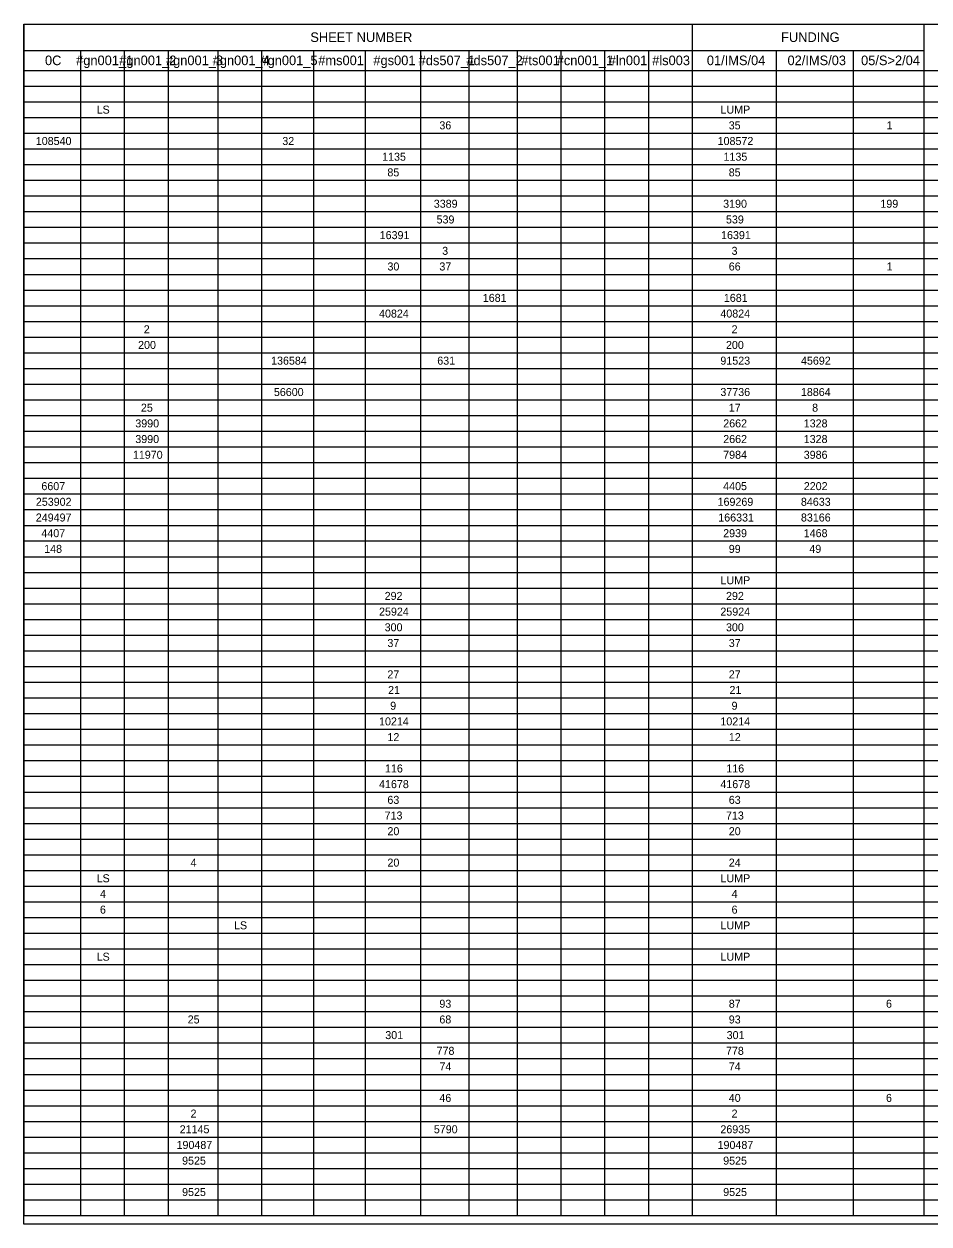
# Model space of a CAD drawing. Extents: x -542 to 295, y -281 to 32.
# Drawn here: x -416.36 to -400.52, y -10.59 to 10.41 of the extents above; entities that cross this region are included whole.
import ezdxf

# ---------------------------------------------------------------- set-up
doc = ezdxf.new("R2010")
doc.units = 0
for name, color, linetype in [('SC_Scratch1', 7, 'Continuous'), ('SH_Data', 7, 'Continuous'), ('SH_Text', 7, 'Continuous')]:
    doc.layers.add(name, color=color, linetype=linetype)

msp = doc.modelspace()

# ---------------------------------------------------------------- linework, layer by layer
at = {"layer": 'SC_Scratch1'}
msp.add_lwpolyline([(-416.359, 10.407), (-385.859, 10.407), (-385.859, -10.593), (-416.359, -10.593)], close=True, dxfattribs=at)
at = {"layer": 'SH_Data'}
for p, q in [((-416.359, 10.407), (-385.859, 10.407)), ((-416.359, 10.407), (-416.359, -10.444)), ((-404.663, 10.407), (-404.663, -10.444)), ((-400.608, 10.407), (-400.608, -10.444)), ((-416.359, 9.946), (-400.608, 9.946)), ((-415.369, 9.946), (-415.369, -10.444)), ((-414.603, 9.946), (-414.603, -10.444)), ((-413.836, 9.946), (-413.836, -10.444)), ((-412.964, 9.946), (-412.964, -10.444)), ((-412.198, 9.946), (-412.198, -10.444)), ((-411.293, 9.946), (-411.293, -10.444)), ((-410.388, 9.946), (-410.388, -10.444)), ((-409.42, 9.946), (-409.42, -10.444)), ((-408.569, 9.946), (-408.569, -10.444)), ((-407.728, 9.946), (-407.728, -10.444)), ((-406.962, 9.946), (-406.962, -10.444)), ((-406.195, 9.946), (-406.195, -10.444)), ((-405.429, 9.946), (-405.429, -10.444)), ((-403.194, 9.946), (-403.194, -10.444)), ((-401.843, 9.946), (-401.843, -10.444)), ((-416.359, 9.595), (-385.859, 9.595)), ((-416.359, 9.32), (-385.859, 9.32)), ((-416.359, 9.046), (-385.859, 9.046)), ((-416.359, 8.771), (-385.859, 8.771)), ((-416.359, 8.497), (-385.859, 8.497)), ((-416.359, 8.222), (-385.859, 8.222)), ((-416.359, 7.948), (-385.859, 7.948)), ((-416.359, 7.673), (-385.859, 7.673)), ((-416.359, 7.399), (-385.859, 7.399)), ((-416.359, 7.124), (-385.859, 7.124)), ((-416.359, 6.85), (-385.859, 6.85)), ((-416.359, 6.575), (-385.859, 6.575)), ((-416.359, 6.301), (-385.859, 6.301)), ((-416.359, 6.026), (-385.859, 6.026)), ((-416.359, 5.752), (-385.859, 5.752)), ((-416.359, 5.477), (-385.859, 5.477)), ((-416.359, 5.203), (-385.859, 5.203)), ((-416.359, 4.928), (-385.859, 4.928)), ((-416.359, 4.654), (-385.859, 4.654)), ((-416.359, 4.379), (-385.859, 4.379)), ((-416.359, 4.105), (-385.859, 4.105)), ((-416.359, 3.83), (-385.859, 3.83)), ((-416.359, 3.556), (-385.859, 3.556)), ((-416.359, 3.281), (-385.859, 3.281)), ((-416.359, 3.007), (-385.859, 3.007)), ((-416.359, 2.732), (-385.859, 2.732)), ((-416.359, 2.458), (-385.859, 2.458)), ((-416.359, 2.183), (-385.859, 2.183)), ((-416.359, 1.909), (-385.859, 1.909)), ((-416.359, 1.634), (-385.859, 1.634)), ((-416.359, 1.36), (-385.859, 1.36)), ((-416.359, 1.085), (-385.859, 1.085)), ((-416.359, 0.811), (-385.859, 0.811)), ((-416.359, 0.536), (-385.859, 0.536)), ((-416.359, 0.262), (-385.859, 0.262)), ((-416.359, -0.013), (-385.859, -0.013)), ((-416.359, -0.287), (-385.859, -0.287)), ((-416.359, -0.562), (-385.859, -0.562)), ((-416.359, -0.836), (-385.859, -0.836)), ((-416.359, -1.111), (-385.859, -1.111)), ((-416.359, -1.385), (-385.859, -1.385)), ((-416.359, -1.66), (-385.859, -1.66)), ((-416.359, -1.935), (-385.859, -1.935)), ((-416.359, -2.209), (-385.859, -2.209)), ((-416.359, -2.484), (-385.859, -2.484)), ((-416.359, -2.758), (-385.859, -2.758)), ((-416.359, -3.033), (-385.859, -3.033)), ((-416.359, -3.307), (-385.859, -3.307)), ((-416.359, -3.582), (-385.859, -3.582)), ((-416.359, -3.856), (-385.859, -3.856)), ((-416.359, -4.131), (-385.859, -4.131)), ((-416.359, -4.405), (-385.859, -4.405)), ((-416.359, -4.68), (-385.859, -4.68)), ((-416.359, -4.954), (-385.859, -4.954)), ((-416.359, -5.229), (-385.859, -5.229)), ((-416.359, -5.503), (-385.859, -5.503)), ((-416.359, -5.778), (-385.859, -5.778)), ((-416.359, -6.052), (-385.859, -6.052)), ((-416.359, -6.327), (-385.859, -6.327)), ((-416.359, -6.601), (-385.859, -6.601)), ((-416.359, -6.876), (-385.859, -6.876)), ((-416.359, -7.15), (-385.859, -7.15)), ((-416.359, -7.425), (-385.859, -7.425)), ((-416.359, -7.699), (-385.859, -7.699)), ((-416.359, -7.974), (-385.859, -7.974)), ((-416.359, -8.248), (-385.859, -8.248)), ((-416.359, -8.523), (-385.859, -8.523)), ((-416.359, -8.797), (-385.859, -8.797)), ((-416.359, -9.072), (-385.859, -9.072)), ((-416.359, -9.346), (-385.859, -9.346)), ((-416.359, -9.621), (-385.859, -9.621)), ((-416.359, -9.895), (-385.859, -9.895)), ((-416.359, -10.17), (-385.859, -10.17)), ((-416.359, -10.444), (-385.859, -10.444))]:
    msp.add_line(p, q, dxfattribs=at)

# ---------------------------------------------------------------- texts
at = {"layer": 'SH_Text'}
for s, height, p in [('SHEET NUMBER', 0.168, (-411.346, 10.093)), ('FUNDING', 0.168, (-403.105, 10.093)), ('0C', 0.168, (-415.991, 9.687)), ('#gn001_1', 0.168, (-415.446, 9.687)), ('#gn001_2', 0.168, (-414.691, 9.687)), ('#gn001_3', 0.168, (-413.873, 9.687)), ('#gn001_4', 0.168, (-413.055, 9.687)), ('#gn001_5', 0.168, (-412.219, 9.687)), ('#ms001', 0.168, (-411.207, 9.687)), ('#gs001', 0.168, (-410.242, 9.687)), ('#ds507_1', 0.168, (-409.449, 9.687)), ('#ds507_2', 0.168, (-408.614, 9.687)), ('#ts001', 0.168, (-407.654, 9.687)), ('#cn001_1', 0.168, (-407.033, 9.687)), ('#ln001', 0.168, (-406.122, 9.687)), ('#ls003', 0.168, (-405.362, 9.687)), ('01/IMS/04', 0.168, (-404.405, 9.687)), ('02/IMS/03', 0.168, (-402.993, 9.687)), ('05/S>2/04', 0.168, (-401.705, 9.687)), ('LS', 0.14, (-415.087, 8.839)), ('LUMP', 0.14, (-404.166, 8.839)), ('36', 0.14, (-409.087, 8.564)), ('35', 0.14, (-404.022, 8.564)), ('1', 0.14, (-401.257, 8.564)), ('108540', 0.14, (-416.152, 8.29)), ('32', 0.14, (-411.837, 8.29)), ('108572', 0.14, (-404.216, 8.29)), ('1135', 0.14, (-410.089, 8.015)), ('1135', 0.14, (-404.113, 8.015)), ('85', 0.14, (-409.997, 7.741)), ('85', 0.14, (-404.022, 7.741)), ('3389', 0.14, (-409.185, 7.192)), ('3190', 0.14, (-404.119, 7.192)), ('199', 0.14, (-401.367, 7.192)), ('539', 0.14, (-409.136, 6.917)), ('539', 0.14, (-404.07, 6.917)), ('16391', 0.14, (-410.132, 6.643)), ('16391', 0.14, (-404.156, 6.643)), ('3', 0.14, (-409.038, 6.368)), ('3', 0.14, (-403.972, 6.368)), ('30', 0.14, (-409.996, 6.094)), ('37', 0.14, (-409.087, 6.094)), ('66', 0.14, (-404.021, 6.094)), ('1', 0.14, (-401.257, 6.094)), ('1681', 0.14, (-408.327, 5.545)), ('1681', 0.14, (-404.107, 5.545)), ('40824', 0.14, (-410.143, 5.27)), ('40824', 0.14, (-404.168, 5.27)), ('2', 0.14, (-414.262, 4.995)), ('2', 0.14, (-403.972, 4.995)), ('200', 0.14, (-414.361, 4.721)), ('200', 0.14, (-404.07, 4.721)), ('136584', 0.14, (-412.033, 4.446)), ('631', 0.14, (-409.124, 4.446)), ('91523', 0.14, (-404.168, 4.446)), ('45692', 0.14, (-402.757, 4.446)), ('56600', 0.14, (-411.984, 3.897)), ('37736', 0.14, (-404.168, 3.897)), ('18864', 0.14, (-402.758, 3.897)), ('25', 0.14, (-414.312, 3.623)), ('17', 0.14, (-404.021, 3.623)), ('8', 0.14, (-402.562, 3.623)), ('3990', 0.14, (-414.41, 3.348)), ('2662', 0.14, (-404.118, 3.348)), ('1328', 0.14, (-402.709, 3.348)), ('3990', 0.14, (-414.41, 3.074)), ('2662', 0.14, (-404.118, 3.074)), ('1328', 0.14, (-402.709, 3.074)), ('11970', 0.14, (-414.452, 2.799)), ('7984', 0.14, (-404.119, 2.799)), ('3986', 0.14, (-402.709, 2.799)), ('6607', 0.14, (-416.054, 2.25)), ('4405', 0.14, (-404.119, 2.25)), ('2202', 0.14, (-402.708, 2.25)), ('253902', 0.14, (-416.151, 1.976)), ('169269', 0.14, (-404.217, 1.976)), ('84633', 0.14, (-402.758, 1.976)), ('249497', 0.14, (-416.152, 1.701)), ('166331', 0.14, (-404.205, 1.701)), ('83166', 0.14, (-402.758, 1.701)), ('4407', 0.14, (-416.054, 1.427)), ('2939', 0.14, (-404.119, 1.427)), ('1468', 0.14, (-402.709, 1.427)), ('148', 0.14, (-416.005, 1.152)), ('99', 0.14, (-404.021, 1.152)), ('49', 0.14, (-402.611, 1.152)), ('LUMP', 0.14, (-404.166, 0.603)), ('292', 0.14, (-410.045, 0.329)), ('292', 0.14, (-404.069, 0.329)), ('25924', 0.14, (-410.143, 0.054)), ('25924', 0.14, (-404.168, 0.054)), ('300', 0.14, (-410.045, -0.22)), ('300', 0.14, (-404.07, -0.22)), ('37', 0.14, (-409.997, -0.495)), ('37', 0.14, (-404.021, -0.495)), ('27', 0.14, (-409.997, -1.044)), ('27', 0.14, (-404.021, -1.044)), ('21', 0.14, (-409.985, -1.318)), ('21', 0.14, (-404.009, -1.318)), ('9', 0.14, (-409.948, -1.593)), ('9', 0.14, (-403.972, -1.593)), ('10214', 0.14, (-410.143, -1.867)), ('10214', 0.14, (-404.168, -1.867)), ('12', 0.14, (-409.996, -2.142)), ('12', 0.14, (-404.02, -2.142)), ('116', 0.14, (-410.039, -2.691)), ('116', 0.14, (-404.064, -2.691)), ('41678', 0.14, (-410.143, -2.965)), ('41678', 0.14, (-404.168, -2.965)), ('63', 0.14, (-409.997, -3.24)), ('63', 0.14, (-404.021, -3.24)), ('713', 0.14, (-410.046, -3.514)), ('713', 0.14, (-404.07, -3.514)), ('20', 0.14, (-409.996, -3.789)), ('20', 0.14, (-404.021, -3.789)), ('4', 0.14, (-413.443, -4.338)), ('20', 0.14, (-409.996, -4.338)), ('24', 0.14, (-404.021, -4.338)), ('LS', 0.14, (-415.087, -4.612)), ('LUMP', 0.14, (-404.166, -4.612)), ('4', 0.14, (-415.029, -4.887)), ('4', 0.14, (-403.972, -4.887)), ('6', 0.14, (-415.029, -5.161)), ('6', 0.14, (-403.972, -5.161)), ('LS', 0.14, (-412.682, -5.436)), ('LUMP', 0.14, (-404.166, -5.436)), ('LS', 0.14, (-415.087, -5.985)), ('LUMP', 0.14, (-404.166, -5.985)), ('93', 0.14, (-409.087, -6.808)), ('87', 0.14, (-404.021, -6.808)), ('6', 0.14, (-401.269, -6.808)), ('25', 0.14, (-413.493, -7.083)), ('68', 0.14, (-409.087, -7.083)), ('93', 0.14, (-404.021, -7.083)), ('301', 0.14, (-410.034, -7.357)), ('301', 0.14, (-404.058, -7.357)), ('778', 0.14, (-409.136, -7.632)), ('778', 0.14, (-404.07, -7.632)), ('74', 0.14, (-409.086, -7.906)), ('74', 0.14, (-404.021, -7.906)), ('46', 0.14, (-409.087, -8.456)), ('40', 0.14, (-404.021, -8.456)), ('6', 0.14, (-401.269, -8.456)), ('2', 0.14, (-413.443, -8.73)), ('2', 0.14, (-403.972, -8.73)), ('21145', 0.14, (-413.633, -9.005)), ('5790', 0.14, (-409.184, -9.005)), ('26935', 0.14, (-404.168, -9.005)), ('190487', 0.14, (-413.688, -9.279)), ('190487', 0.14, (-404.217, -9.279)), ('9525', 0.14, (-413.591, -9.554)), ('9525', 0.14, (-404.119, -9.554)), ('9525', 0.14, (-413.591, -10.103)), ('9525', 0.14, (-404.119, -10.103))]:
    msp.add_text(s, height=height, dxfattribs=at).set_placement(p)

doc.saveas('drawing.dxf')
